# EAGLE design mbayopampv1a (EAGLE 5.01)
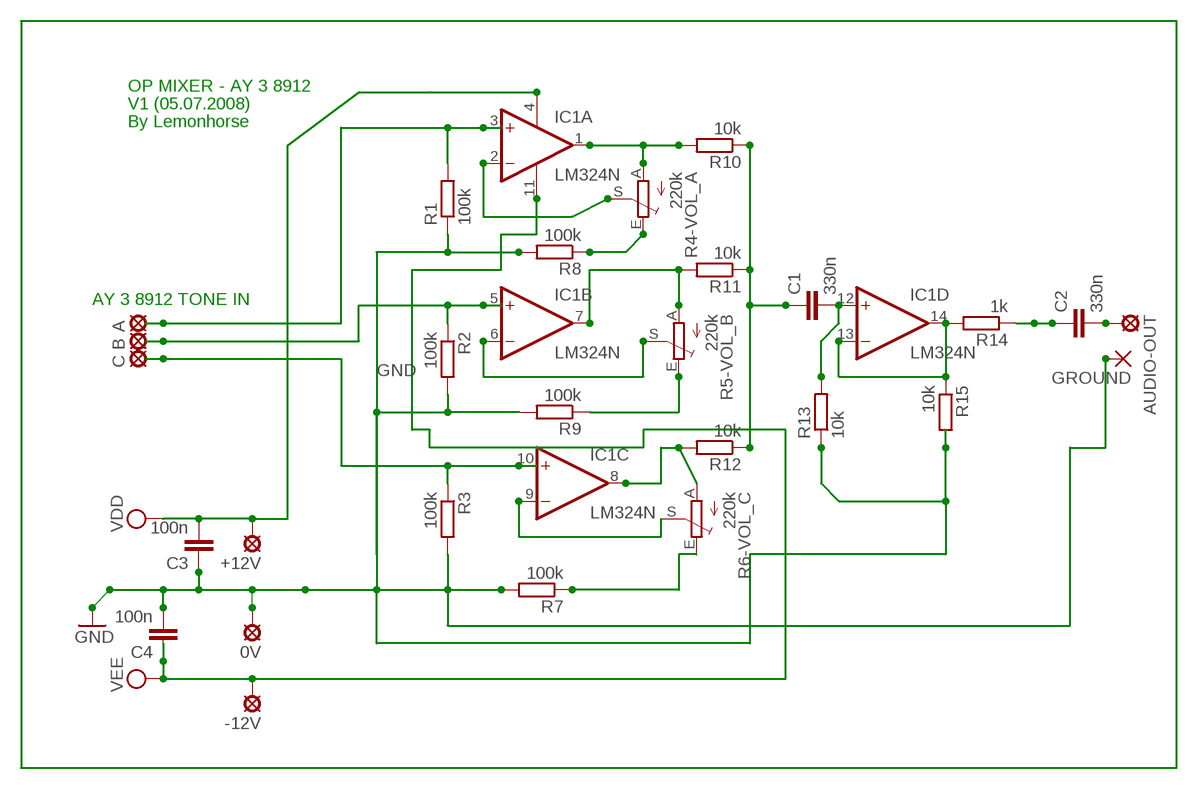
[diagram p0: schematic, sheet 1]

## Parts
0V  MCS08  [MCS08]
+12V  MCS08  [MCS08]
-12V  MCS08  [MCS08]
A  A  MCS08  [MCS08]
AUDIO-OUT  MCS08  [MCS08]
B  B  MCS08  [MCS08]
C  C  MCS08  [MCS08]
C1  330n  C-EU050-024X044  [C050-024X044]
C2  330n  C-EU050-024X044  [C050-024X044]
C3  100n  C-EU050-024X044  [C050-024X044]
C4  100n  C-EU050-024X044  [C050-024X044]
GROUND  WIREPAD2,54/1,0  [2,54/1,0]
IC1  LM324N  [DIL14]
R1  100k  R-EU_0204/7  [0204/7]
R2  100k  R-EU_0207/10  [0207/10]
R3  100k  R-EU_0207/10  [0207/10]
R4-VOL_A  220k  TRIM_EU-CA6H  [CA6H]
R5-VOL_B  220k  TRIM_EU-CA6H  [CA6H]
R6-VOL_C  220k  TRIM_EU-CA6H  [CA6H]
R7  100k  R-EU_0207/10  [0207/10]
R8  100k  R-EU_0207/10  [0207/10]
R9  100k  R-EU_0207/10  [0207/10]
R10  10k  R-EU_0207/10  [0207/10]
R11  10k  R-EU_0207/10  [0207/10]
R12  10k  R-EU_0207/10  [0207/10]
R13  10k  R-EU_0207/10  [0207/10]
R14  1k  R-EU_0207/10  [0207/10]
R15  10k  R-EU_0207/10  [0207/10]

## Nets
A: A.MP IC1.3(A:+IN) R1.2
ABCMIX: C1.1 R10.1 R11.1 R12.1
ABCOUT: AUDIO-OUT.MP C2.2
B: B.MP IC1.5(B:+IN) R2.1
C: C.MP IC1.10(C:+IN) R3.1
GND: 0V.MP C3.1 C4.2 GROUND.1(P) R1.1 R2.2 R3.2 R7.2 R8.2 R9.2 R13.1 R15.2
N$2: R6-VOL_C.E R7.1
N$11: IC1.6(B:-IN) R5-VOL_B.S
N$12: IC1.9(C:-IN) R6-VOL_C.S
N$13: IC1.2(A:-IN) R4-VOL_A.S
N$18: R5-VOL_B.E R9.1
N$19: R4-VOL_A.E R8.1
N$22: C1.2 IC1.12(D:+IN) R13.2
N$25: IC1.13(D:-IN) IC1.14(D:OUT) R14.2 R15.1
OUT: C2.1 R14.1
OUTA: IC1.1(A:OUT) R4-VOL_A.A R10.2
OUTB: IC1.7(B:OUT) R5-VOL_B.A R11.2
OUTC: IC1.8(C:OUT) R6-VOL_C.A R12.2
VDD: +12V.MP C3.2 IC1.4(P:V+)
VEE: -12V.MP C4.1 IC1.11(P:V-)

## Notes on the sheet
- OP MIXER - AY 3 8912
- V1 (05.07.2008)
- By Lemonhorse
- AY 3 8912 TONE IN

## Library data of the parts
0V +12V -12V A AUDIO-OUT B C = solpad:MCS08: SOLDER PAD
C1-C4 = rcl:C-EU: CAPACITOR, European symbol
GROUND = wirepad:WIREPAD: Wire PAD connect wire on PCB
IC1 = linear:LM324: OP AMP
R1-R3 R7-R15 = rcl:R-EU_: RESISTOR, European symbol
R4-VOL_A R5-VOL_B R6-VOL_C = pot:TRIM_EU-: POTENTIOMETER

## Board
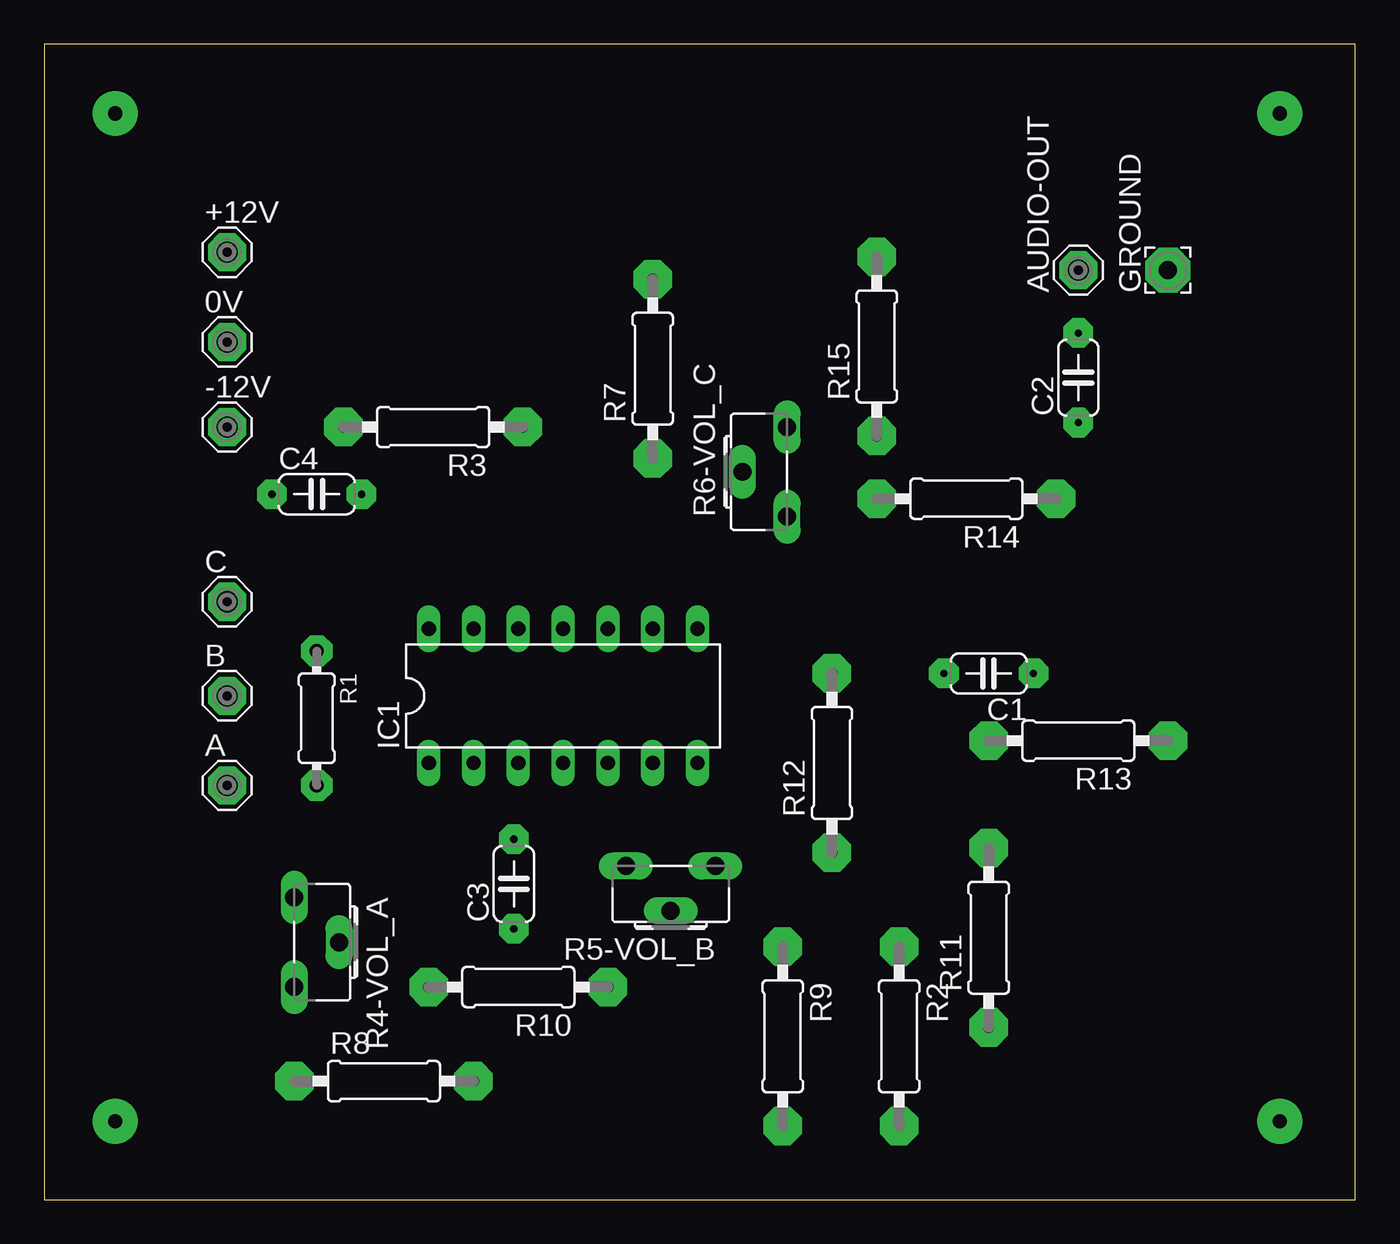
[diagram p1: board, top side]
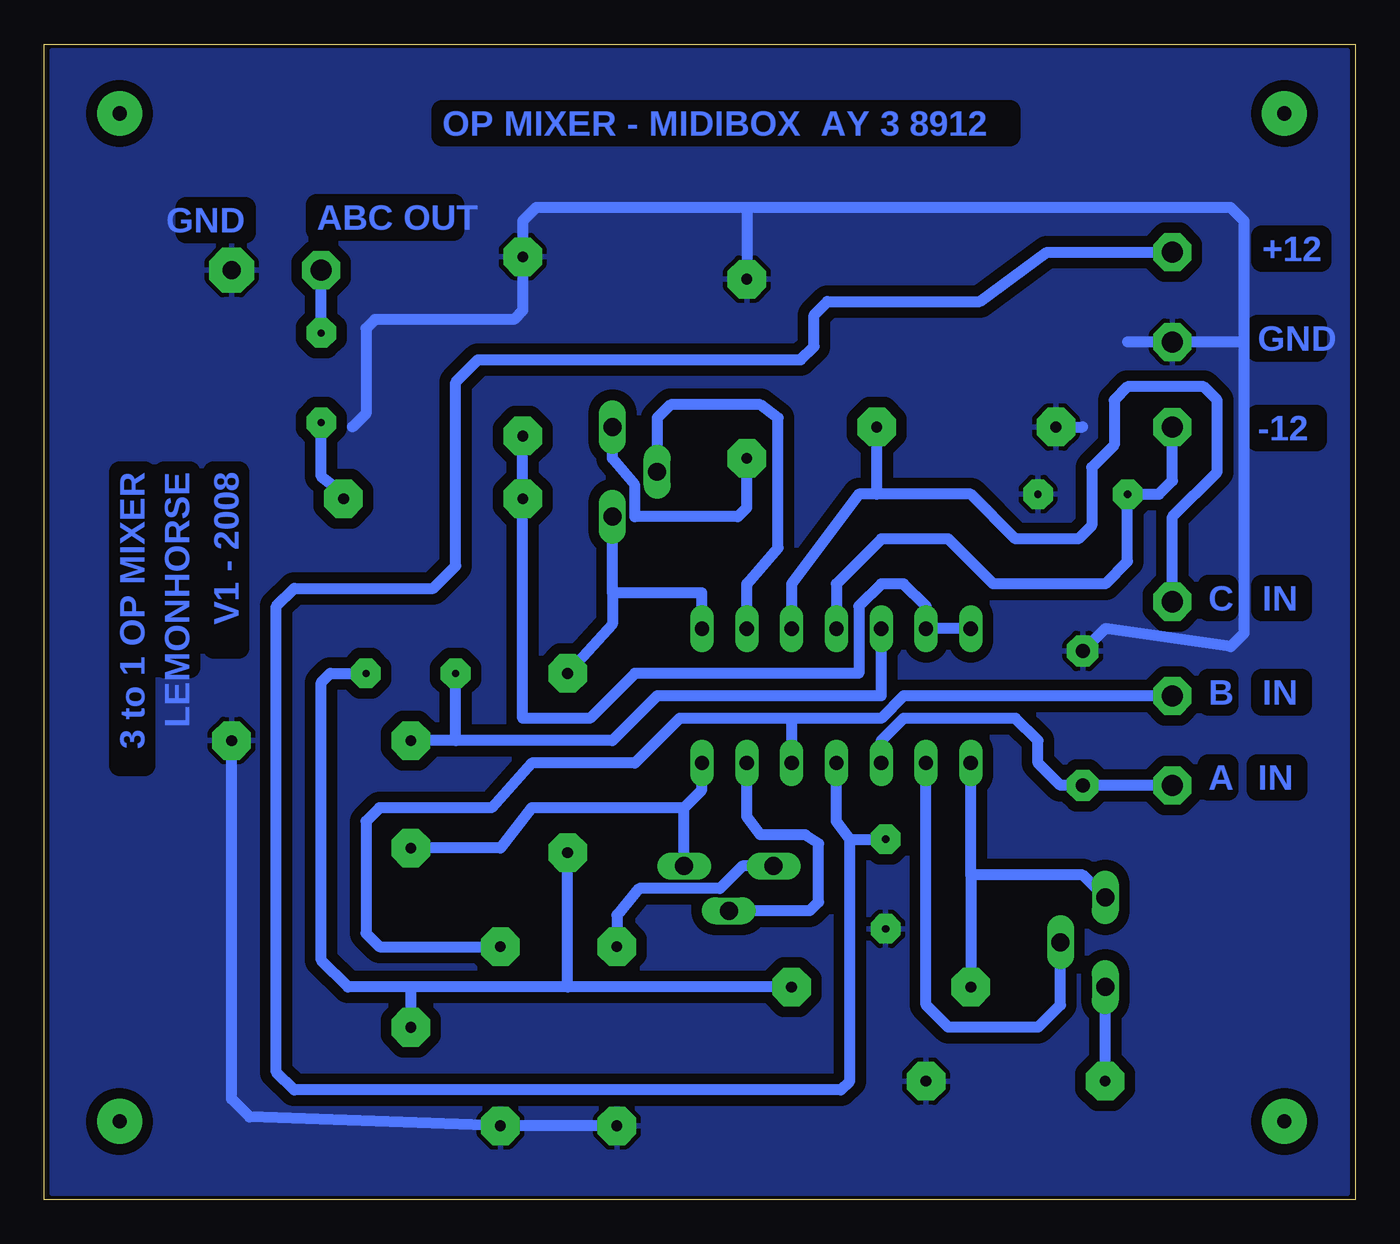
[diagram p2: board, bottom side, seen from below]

Size 74.35 x 65.52 mm. Coordinates in mm from the lower left corner, seen from the top.
Outline: 0,0 74.35,0 74.35,65.52 0,65.52 0,0
Copper layers (1*16): Top 0.055mm / dielectric 1.5mm / Bottom 0.055mm
Design rules "default *": minimum track width 10mil, minimum drill 24mil, track to track 8mil, track to pad 8mil, pad to pad 8mil, via to via 8mil, smd to smd 8mil, copper to edge 0mil, drill to drill 8mil, minimum pad ring 10mil, minimum via ring 8mil, stop-mask expansion 4mil, vias tented up to drill 0mil, thermal gap 10mil

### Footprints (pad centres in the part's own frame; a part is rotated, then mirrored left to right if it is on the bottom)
MCS08 = drill 1.194 pad 2.159 octagon: MP 0,0
C050-024X044 = drill 0.406 pad 1.676 octagon: 1 -2.54,0; 2 2.54,0
2,54/1,0 = drill 1.016 pad 2.54 octagon: 1 0,0
DIL14 = drill 0.813 long: 1 -7.62,-3.81; 2 -5.08,-3.81; 3 -2.54,-3.81; 4 0,-3.81; 5 2.54,-3.81; 6 5.08,-3.81; 7 7.62,-3.81; 8 7.62,3.81; 9 5.08,3.81; 10 2.54,3.81; 11 0,3.81; 12 -2.54,3.81; 13 -5.08,3.81; 14 -7.62,3.81
0204/7 = drill 0.813 pad 1.778 octagon: 1 -3.81,0; 2 3.81,0
0207/10 = drill 0.61 pad 2.184 octagon: 1 -5.08,0; 2 5.08,0
CA6H = drill 1.016 long: A -2.54,0; E 2.54,0; S 0,2.54

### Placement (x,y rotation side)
0V  10.38,48.64 0 top
+12V  10.38,53.72 0 top
-12V  10.38,43.81 0 top
A  10.38,23.49 0 top
AUDIO-OUT  58.64,52.7 90 top
B  10.38,28.57 0 top
C  10.38,33.9 0 top
C1  53.56,29.84 180 top
C2  58.64,46.6 90 top
C3  26.63,17.9 90 top
C4  15.46,40 0 top
GROUND  63.72,52.7 90 top
IC1  29.43,28.57 0 top
R1  15.46,27.3 270 top
R2  48.48,9.27 270 top
R3  22.06,43.81 180 top
R4-VOL_A  14.19,14.6 270 top
R5-VOL_B  35.52,18.92 180 top
R6-VOL_C  42.13,41.27 90 top
R7  34.51,47.11 90 top
R8  19.27,6.73 0 top
R9  41.87,9.27 270 top
R10  26.89,12.06 180 top
R11  53.56,14.85 90 top
R12  44.67,24.76 90 top
R13  58.64,26.03 180 top
R14  52.29,39.75 180 top
R15  47.21,48.38 90 top

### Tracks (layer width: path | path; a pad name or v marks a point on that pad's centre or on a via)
A
  Bottom 0.61: A.MP R1.2 16.73,23.49 18,24.76 18,26.03 19.27,27.3 25.62,27.3 26.89,26.03 IC1.3
ABCMIX
  Bottom 0.61: 44.67,12.06 R12.1 | C1.1 58.13,29.84 58.64,29.33 58.64,13.58 57.11,12.06 53.56,12.06 | 44.67,12.06 53.56,12.06 | R10.1 44.67,12.06 | 53.56,12.06 R11.1
ABCOUT
  Bottom 0.61: C2.2 AUDIO-OUT.MP
B
  Bottom 0.61: R2.1 55.33,14.35 56.1,15.11 56.1,21.46 55.33,22.22 48.98,22.22 46.7,24.76 40.86,24.76 38.32,27.3 31.97,27.3 | 31.97,27.3 IC1.5 | B.MP 25.62,28.57 26.89,27.3 31.97,27.3
C
  Bottom 0.61: 27.14,40 R3.1 | 27.14,40 28.16,40 31.97,34.92 IC1.10 | C.MP 10.38,38.73 7.84,41.27 7.84,45.33 8.6,46.1 12.92,46.1 13.68,45.33 13.68,42.79 14.95,41.52 14.95,38.22 15.71,37.46 19.27,37.46 21.81,40 27.14,40
GND
  Bottom 0.61: R3.2 15.46,43.81 | R9.2 R2.2 62.7,4.69 63.72,5.71 R13.1 | R1.1 14.19,32.38 7.07,31.36 6.31,32.13 6.31,48.64 | 0V.MP 12.92,48.64 | 6.31,48.64 0V.MP | 34.51,56.26 46.44,56.26 47.21,55.49 R15.2 47.21,50.41 47.71,49.91 55.59,49.91 56.1,49.4 56.1,44.57 56.86,43.81 | 34.51,56.26 R7.2 | 6.31,48.64 0V.MP | 6.31,48.64 6.31,55.49 7.07,56.26 34.51,56.26
  pour Bottom (isolate 0.61): 0.47,0.38 73.88,0.38 73.88,65.15 0.47,65.15
N$2
  Bottom 0.61: R7.1 34.51,39.24 35.01,38.73 40.86,38.73 40.86,40.51 42.13,42.03 R6-VOL_C.E
N$3  (via drill 0.8 pad 2.54)
  other vias: 4.03,61.59
N$5  (via drill 0.8 pad 2.54)
  other vias: 4.03,4.44
N$7  (via drill 0.8 pad 2.54)
  other vias: 70.07,4.44
N$8  (via drill 0.8 pad 2.54)
  other vias: 70.07,61.59
N$11
  Bottom 0.61: IC1.6 34.51,21.71 33.74,20.7 31.46,20.7 31.2,20.7 30.44,20.19 30.44,16.89 30.95,16.38 R5-VOL_B.S
N$12
  Bottom 0.61: IC1.9 34.51,34.92 32.73,36.95 32.73,44.32 33.74,45.08 38.82,45.08 39.59,44.32 R6-VOL_C.S
N$13
  Bottom 0.61: R4-VOL_A.S 16.73,11.04 18,9.77 23.08,9.77 24.35,11.04 IC1.2
N$18
  Bottom 0.61: R9.1 41.87,16.12 40.6,17.65 36.03,17.65 34.76,18.92 R5-VOL_B.E
N$19
  Bottom 0.61: R8.1 R4-VOL_A.E
N$22
  Bottom 0.61: 51.02,26.03 42.13,26.03 39.59,28.57 26.89,28.57 IC1.12 | 51.02,26.03 C1.2 | 51.02,26.03 R13.2
N$25
  Bottom 0.61: IC1.14 IC1.13 24.35,33.65 25.62,34.92 26.89,34.92 28.16,33.65 28.16,29.84 40.86,29.84 43.4,27.3 47.21,27.3 R14.2 R15.1
OUT
  Bottom 0.61: C2.1 58.64,41.02 57.37,40 R14.1
OUTA
  Bottom 0.61: 21.81,18.41 R10.2 | 21.81,18.41 IC1.1 | R4-VOL_A.A 15.46,18.41 21.81,18.41
OUTB
  Bottom 0.61: R11.2 48.48,19.93 46.7,22.22 38.06,22.22 | 38.06,22.22 37.05,23.24 IC1.7 | R5-VOL_B.A 38.06,22.22
OUTC
  Bottom 0.61: IC1.8 37.05,34.41 42.13,34.41 | 42.13,34.41 R6-VOL_C.A | 42.13,34.41 42.13,32.63 R12.2
VDD
  Bottom 0.61: 28.66,20.44 28.66,6.73 29.17,6.22 60.16,6.22 61.18,7.23 61.18,33.65 60.16,34.67 52.29,34.67 51.02,35.94 51.02,46.35 49.75,47.62 31.46,47.62 30.7,48.38 30.7,50.16 29.93,50.92 21.3,50.92 17.49,53.72 +12V.MP | 28.66,20.44 29.43,21.46 IC1.4 | 28.66,20.44 C3.2
VEE
  Bottom 0.61: IC1.11 29.43,34.92 26.89,37.46 23.08,37.46 20.54,34.92 14.19,34.92 12.92,36.19 C4.1 11.14,40 10.38,40.76 -12V.MP

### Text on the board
Bottom: OP MIXER - MIDIBOX AY 3 8912 | GND | ABC OUT | +12 | GND | -12 | V1 - 2008 | LEMONHORSE | 3 to 1 OP MIXER | IN | C | IN | B | IN | A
